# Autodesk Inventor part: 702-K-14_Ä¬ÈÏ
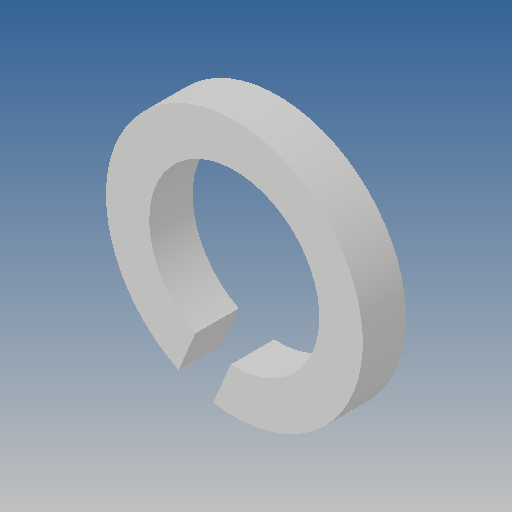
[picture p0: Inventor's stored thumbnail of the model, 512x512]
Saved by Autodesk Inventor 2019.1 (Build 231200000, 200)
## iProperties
Created: 2010-06
Part Number: 702-K-14_Ä¬ÈÏ
Material: Ogólny
Document SubType Name: Modeling
Designer: CADENGINEERING4
Density: 1 g/cm^3
Appearance: Domyślna
Author: CADENGINEERING4
Revision Number: ÈÎºÎ
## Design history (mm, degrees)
feature "NONE"
node "Bryła1"
